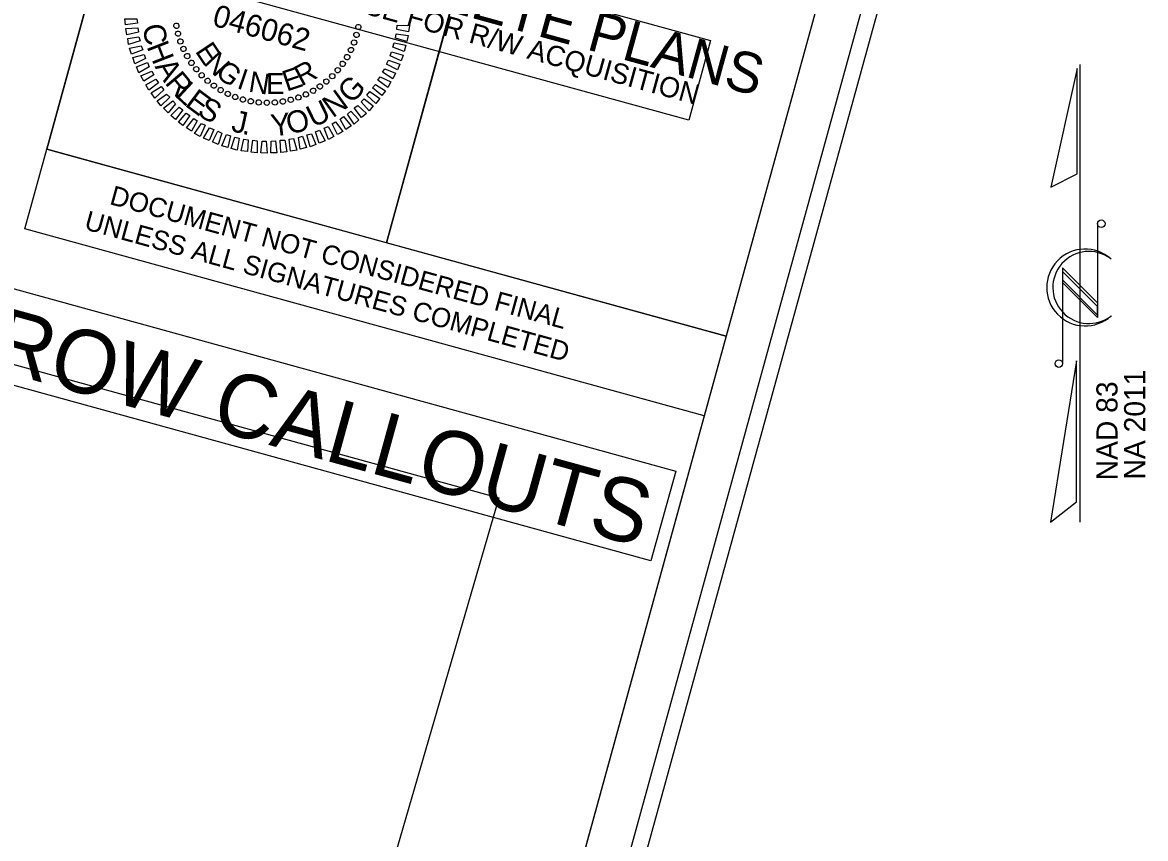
# Model space of a CAD drawing. Extents: x 1641192 to 2864602, y 841295 to 973236.
# Drawn here: x 1642843.9 to 1643162.7, y 842046.5 to 842278.3 of the extents above; entities that cross this region are included whole.
import ezdxf

# ---------------------------------------------------------------- set-up
doc = ezdxf.new("R2010")
doc.units = 0
for name, color, linetype in [('Default', 7, 'Continuous'), ('Old_Level_2', 7, 'Continuous'), ('Prop DSN White Annotation Label', 7, 'Continuous'), ('Sheet Clip Boundary CELL', 7, 'Continuous'), ('Sheet North Arrow CELL', 7, 'Continuous'), ('Sheet Plan CELL', 7, 'Continuous'), ('Sheet Plot Border Inside CELL', 7, 'Continuous'), ('Sheet Plot Border Outside CELL', 7, 'Continuous'), ('Sheet Sticker Exception Certification CELL', 7, 'Continuous'), ('Sheet Sticker Incomplete CELL', 7, 'Continuous')]:
    doc.layers.add(name, color=color, linetype=linetype)

msp = doc.modelspace()

# ---------------------------------------------------------------- linework, layer by layer
at = {"layer": 'Old_Level_2'}
for p, q in [((1642887.5, 842277.32), (1642887.5, 842277.32)), ((1642939.23, 842276.95), (1642939.23, 842276.95)), ((1642888.01, 842275.08), (1642888.01, 842275.08)), ((1642888.68, 842272.86), (1642888.68, 842272.86)), ((1642937.99, 842272.52), (1642937.99, 842272.52)), ((1642938.71, 842274.71), (1642938.71, 842274.71)), ((1642889.49, 842270.76), (1642889.49, 842270.76)), ((1642937.07, 842270.43), (1642937.07, 842270.43)), ((1642890.58, 842268.7), (1642890.58, 842268.7)), ((1642891.76, 842266.78), (1642891.76, 842266.78)), ((1642934.82, 842266.48), (1642934.82, 842266.48)), ((1642936.07, 842268.42), (1642936.07, 842268.42)), ((1642893.19, 842264.95), (1642893.19, 842264.95)), ((1642894.68, 842263.22), (1642894.68, 842263.22)), ((1642931.87, 842262.97), (1642931.87, 842262.97)), ((1642933.39, 842264.68), (1642933.39, 842264.68)), ((1642896.4, 842261.7), (1642896.4, 842261.7)), ((1642898.19, 842260.27), (1642898.19, 842260.27)), ((1642928.31, 842260.05), (1642928.31, 842260.05)), ((1642930.13, 842261.47), (1642930.13, 842261.47)), ((1642900.14, 842259.01), (1642900.14, 842259.01)), ((1642902.15, 842258.01), (1642902.15, 842258.01)), ((1642904.23, 842257.1), (1642904.23, 842257.1)), ((1642906.42, 842256.38), (1642906.42, 842256.38)), ((1642922.23, 842256.96), (1642922.23, 842256.96)), ((1642924.33, 842257.78), (1642924.33, 842257.78)), ((1642926.39, 842258.87), (1642926.39, 842258.87)), ((1642908.66, 842255.86), (1642908.66, 842255.86)), ((1642910.92, 842255.6), (1642910.92, 842255.6)), ((1642913.25, 842255.43), (1642913.25, 842255.43)), ((1642915.54, 842255.5), (1642915.54, 842255.5)), ((1642917.77, 842255.79), (1642917.77, 842255.79)), ((1642920.01, 842256.29), (1642920.01, 842256.29))]:
    msp.add_line(p, q, dxfattribs=at)
for points in [[(1642876.53, 842278.08), (1642873.1, 842277.56), (1642872.94, 842279.27), (1642876.29, 842279.27)], [(1642876.83, 842275.47), (1642873.45, 842274.71), (1642873.21, 842276.5), (1642876.61, 842276.71)], [(1642950.28, 842277.52), (1642953.75, 842277.38), (1642953.46, 842275.62), (1642950.17, 842276.25)], [(1642877.28, 842273.03), (1642873.99, 842271.98), (1642873.73, 842273.72), (1642876.92, 842274.15)], [(1642949.36, 842272.46), (1642952.69, 842271.77), (1642952.25, 842270.05), (1642949.05, 842271.25)], [(1642949.96, 842275.01), (1642953.36, 842274.57), (1642953.02, 842272.82), (1642949.75, 842273.77)], [(1642878.03, 842270.46), (1642874.85, 842269.23), (1642874.28, 842270.99), (1642877.58, 842271.66)], [(1642878.81, 842268.05), (1642875.78, 842266.56), (1642875.2, 842268.27), (1642878.45, 842269.17)], [(1642948.66, 842269.94), (1642951.93, 842269), (1642951.4, 842267.35), (1642948.25, 842268.75)], [(1642879.82, 842265.68), (1642876.91, 842264), (1642876.2, 842265.64), (1642879.37, 842266.88)], [(1642947.78, 842267.58), (1642950.95, 842266.44), (1642950.3, 842264.77), (1642947.22, 842266.43)], [(1642881.13, 842263.4), (1642878.34, 842261.58), (1642877.44, 842263.11), (1642880.58, 842264.41)], [(1642945.43, 842262.83), (1642948.41, 842261.37), (1642947.62, 842259.79), (1642944.76, 842261.87)], [(1642946.72, 842265.1), (1642949.75, 842263.89), (1642948.96, 842262.25), (1642946.04, 842264.14)], [(1642882.5, 842261.16), (1642879.74, 842259.06), (1642878.84, 842260.59), (1642881.73, 842262.17)], [(1642884.02, 842259.1), (1642881.43, 842256.8), (1642880.4, 842258.25), (1642883.24, 842260.06)], [(1642944.05, 842260.6), (1642946.96, 842258.88), (1642945.9, 842257.48), (1642943.22, 842259.68)], [(1642885.71, 842257.05), (1642883.18, 842254.57), (1642882.13, 842255.97), (1642884.75, 842257.94)], [(1642940.86, 842256.56), (1642943.42, 842254.55), (1642942.26, 842253.18), (1642940, 842255.75)], [(1642942.47, 842258.63), (1642945.31, 842256.66), (1642944.15, 842255.28), (1642941.67, 842257.64)], [(1642887.33, 842255.17), (1642885.22, 842252.64), (1642883.92, 842253.89), (1642886.52, 842256.03)], [(1642889.36, 842253.41), (1642887.33, 842250.75), (1642885.94, 842251.86), (1642888.39, 842254.25)], [(1642939.08, 842254.69), (1642941.53, 842252.45), (1642940.15, 842251.29), (1642938.04, 842253.99)], [(1642891.39, 842251.86), (1642889.41, 842248.97), (1642888.15, 842249.94), (1642890.32, 842252.52)], [(1642893.44, 842250.37), (1642891.87, 842247.42), (1642890.43, 842248.33), (1642892.47, 842251)], [(1642932.76, 842250.05), (1642934.81, 842247.31), (1642933.25, 842246.47), (1642931.75, 842249.45)], [(1642935.03, 842251.52), (1642937.16, 842248.87), (1642935.7, 842247.84), (1642934.09, 842250.79)], [(1642937.04, 842253.06), (1642939.34, 842250.63), (1642938, 842249.41), (1642936.14, 842252.26)], [(1642895.7, 842249.09), (1642894.35, 842245.92), (1642892.73, 842246.77), (1642894.7, 842249.61)], [(1642898.14, 842247.87), (1642896.85, 842244.74), (1642895.25, 842245.42), (1642896.96, 842248.33)], [(1642900.47, 842246.84), (1642899.42, 842243.6), (1642897.83, 842244.33), (1642899.3, 842247.35)], [(1642928.21, 842247.66), (1642929.76, 842244.67), (1642928.12, 842243.96), (1642927.08, 842247.25)], [(1642930.64, 842248.71), (1642932.29, 842245.91), (1642930.77, 842245), (1642929.49, 842248.25)], [(1642902.96, 842246.04), (1642902.12, 842242.74), (1642900.46, 842243.22), (1642901.76, 842246.4)], [(1642905.38, 842245.36), (1642904.79, 842242.01), (1642903.13, 842242.48), (1642904.18, 842245.72)], [(1642907.98, 842244.97), (1642907.7, 842241.58), (1642905.93, 842241.82), (1642906.72, 842245.13)], [(1642910.49, 842244.65), (1642910.46, 842241.2), (1642908.75, 842241.47), (1642909.23, 842244.81)], [(1642913.06, 842244.58), (1642913.31, 842241.12), (1642911.49, 842241.2), (1642911.93, 842244.6)], [(1642915.66, 842244.61), (1642916.05, 842241.28), (1642914.36, 842241.22), (1642914.51, 842244.53)], [(1642918.35, 842244.79), (1642918.91, 842241.51), (1642917.24, 842241.3), (1642917.01, 842244.81)], [(1642920.85, 842245.28), (1642921.74, 842242.03), (1642919.99, 842241.72), (1642919.62, 842245.11)], [(1642923.34, 842245.94), (1642924.51, 842242.72), (1642922.74, 842242.31), (1642922.22, 842245.58)], [(1642925.89, 842246.63), (1642927.11, 842243.57), (1642925.54, 842242.94), (1642924.62, 842246.31)]]:
    msp.add_lwpolyline(points, close=True, dxfattribs=at)
for centre, major_axis in [((1642887.54, 842277.31), (-0.742, -0.126)), ((1642888.02, 842275.07), (-0.729, -0.19)), ((1642938.69, 842274.73), (0.726, -0.2)), ((1642939.2, 842276.96), (0.741, -0.136)), ((1642888.69, 842272.88), (-0.709, -0.253)), ((1642937.99, 842272.55), (0.706, -0.262)), ((1642889.56, 842270.76), (-0.685, -0.314)), ((1642890.6, 842268.72), (-0.655, -0.372)), ((1642936.03, 842268.42), (0.65, -0.381)), ((1642937.1, 842270.44), (0.68, -0.323)), ((1642891.82, 842266.79), (-0.62, -0.428)), ((1642934.78, 842266.5), (0.614, -0.436)), ((1642893.2, 842264.96), (-0.58, -0.48)), ((1642894.73, 842263.26), (-0.536, -0.529)), ((1642931.82, 842263.01), (0.529, -0.536)), ((1642933.38, 842264.69), (0.574, -0.488)), ((1642896.41, 842261.71), (-0.488, -0.574)), ((1642898.21, 842260.3), (-0.436, -0.614)), ((1642900.13, 842259.06), (-0.381, -0.65)), ((1642926.36, 842258.88), (0.372, -0.655)), ((1642928.3, 842260.1), (0.428, -0.62)), ((1642930.12, 842261.48), (0.48, -0.58)), ((1642902.16, 842257.99), (-0.323, -0.68)), ((1642904.26, 842257.1), (-0.262, -0.706)), ((1642906.44, 842256.4), (-0.2, -0.726)), ((1642908.67, 842255.89), (-0.136, -0.741)), ((1642910.94, 842255.57), (-0.071, -0.75)), ((1642917.78, 842255.83), (0.126, -0.742)), ((1642920.02, 842256.31), (0.19, -0.729)), ((1642922.2, 842256.98), (0.253, -0.709)), ((1642924.32, 842257.84), (0.314, -0.685)), ((1642913.22, 842255.46), (-0.005, -0.753)), ((1642915.51, 842255.54), (0.061, -0.751))]:
    msp.add_ellipse(centre, major_axis=major_axis, ratio=0.999708, dxfattribs=at)
at = {"layer": 'Prop DSN White Annotation Label'}
msp.add_lwpolyline([(1642839.77, 842203.05), (1643029.31, 842150.89), (1643022.29, 842125.36), (1642832.75, 842177.53)], close=True, dxfattribs=at)
at = {"layer": 'Sheet Clip Boundary CELL'}
msp.add_lwpolyline([(1642834.84, 842332.26), (1642796.64, 842193.46), (1642979.12, 842143.25), (1642931.91, 841980.78), (1642684.68, 842016.94), (1642616.55, 841780.17), (1642867.94, 841712.2), (1642769.91, 841383), (1642620.74, 841424.05), (1642612.78, 841395.12), (1641412.11, 841725.54), (1641476.31, 841958.82), (1641627.07, 841958.82), (1641755.49, 842119.21), (1641752.38, 842181.83), (1641796.56, 842667.29)], dxfattribs=at)
at = {"layer": 'Sheet North Arrow CELL'}
for p, q in [((1643144.19, 842136.37), (1643144.19, 842266.37)), ((1643149.09, 842221.13), (1643149.09, 842194.45)), ((1643149.09, 842198.61), (1643139.15, 842208.55)), ((1643139.15, 842208.55), (1643139.15, 842181.43)), ((1643152.77, 842211.19), (1643152.91, 842211.09)), ((1643149.09, 842197.63), (1643139.15, 842207.57)), ((1643139.15, 842207.57), (1643139.15, 842205.13)), ((1643149.09, 842195.19), (1643139.15, 842205.13)), ((1643139.15, 842205.13), (1643149.09, 842195.19)), ((1643149.09, 842194.45), (1643139.15, 842204.39)), ((1643149.09, 842195.19), (1643149.09, 842197.63))]:
    msp.add_line(p, q, dxfattribs=at)
for points in [[(1643143.29, 842265.23), (1643135.87, 842231.47), (1643143.29, 842235.23)], [(1643143.13, 842182.17), (1643135.77, 842136.37), (1643143.13, 842142.17)]]:
    msp.add_lwpolyline(points, close=True, dxfattribs=at)
for centre in [(1643150.15, 842221.11), (1643138.09, 842181.39)]:
    msp.add_circle(centre, 1.06, dxfattribs=at)
for centre, radius, start, end in [((1643145.57, 842203), 10.92, 47.84, 312.3941), ((1643146.63, 842203), 10.24, 53.095, 308.6287)]:
    msp.add_arc(centre, radius, start, end, dxfattribs=at)
at = {"layer": 'Sheet Plan CELL'}
msp.add_line((1642977.06, 842324.21), (1642947.23, 842215.77), dxfattribs=at)
for points in [[(1643083.47, 842333.88), (1641637.2, 842731.89), (1641358.6, 841719.52), (1642804.85, 841321.52)], [(1641358.6, 841719.52), (1641637.16, 842731.87), (1642890.57, 842386.98), (1642850.76, 842242.29), (1643043.63, 842189.2), (1642804.85, 841321.52)], [(1642880.6, 842350.75), (1642977.06, 842324.21), (1642947.21, 842215.73), (1642850.76, 842242.29)], [(1642977.06, 842324.21), (1643073.47, 842297.69), (1643043.63, 842189.2), (1642947.21, 842215.73)]]:
    msp.add_lwpolyline(points, close=True, dxfattribs=at)
at = {"layer": 'Sheet Plot Border Inside CELL'}
msp.add_lwpolyline([(1641209.95, 841757.82), (1642816.23, 841315.8), (1643096.16, 842332.97), (1641489.87, 842775.01)], close=True, dxfattribs=at)
at = {"layer": 'Sheet Plot Border Outside CELL'}
msp.add_lwpolyline([(1641192.11, 841741.99), (1642815.27, 841295.31), (1643105.8, 842351.06), (1641482.64, 842797.74)], close=True, dxfattribs=at)
msp.add_lwpolyline([(1641192.11, 841741.99), (1642815.27, 841295.31), (1643105.8, 842351.06), (1641482.64, 842797.74)], close=True, dxfattribs=at)
at = {"layer": 'Sheet Sticker Exception Certification CELL'}
for p, q in [((1642844.53, 842219.63), (1642850.76, 842242.29)), ((1642844.53, 842219.63), (1642850.76, 842242.29)), ((1642850.76, 842242.29), (1643043.63, 842189.22)), ((1642850.76, 842242.29), (1643043.63, 842189.22)), ((1643037.4, 842166.56), (1642844.53, 842219.63)), ((1643037.4, 842166.56), (1642844.53, 842219.63)), ((1643043.63, 842189.2), (1643037.39, 842166.55)), ((1643043.63, 842189.2), (1643037.39, 842166.55))]:
    msp.add_line(p, q, dxfattribs=at)
at = {"layer": 'Sheet Sticker Incomplete CELL'}
msp.add_lwpolyline([(1642891.27, 842289.47), (1642897.51, 842312.13), (1643039.24, 842273.13), (1643033, 842250.47)], close=True, dxfattribs=at)

# ---------------------------------------------------------------- texts
at = {"layer": 'Default'}
for s, rotation, p in [('C', 281.8134, (1642877.83, 842277.23)), ('H', 291.2571, (1642879.04, 842271.46)), ('A', 301.0969, (1642881.29, 842265.73)), ('R', 309.8096, (1642884.07, 842261.05)), ('G', 46.4133, (1642937.26, 842254.9)), ('L', 317.1818, (1642886.96, 842257.46)), ('E', 323.366, (1642889.72, 842254.75)), ('S', 330.3726, (1642893.18, 842252.06)), ('N', 35.8424, (1642931.94, 842250.98)), ('O', 14.6548, (1642919.6, 842246.35)), ('U', 26.0482, (1642926.45, 842248.27)), ('J', 347.6456, (1642902.88, 842247.39)), ('Y', 6.8561, (1642914.75, 842245.84)), ('.', 352.8275, (1642906.02, 842246.58))]:
    msp.add_text(s, height=6.27, rotation=rotation, dxfattribs=at).set_placement(p)
at = {"layer": 'Old_Level_2'}
for s, height, rotation, p in [('046062', 6.275, 344.6135, (1642897.46, 842277.44)), ('E', 5.9, 303.8904, (1642892.72, 842270.09)), ('N', 5.9, 313.2475, (1642895.06, 842266.58)), ('G', 5.9, 322.6037, (1642898.32, 842263.31)), ('R', 5.9, 28.0949, (1642923.07, 842260.04)), ('I', 5.9, 341.3147, (1642904.47, 842259.69)), ('N', 5.9, 350.6699, (1642907.82, 842258.66)), ('E', 5.9, 0.0253, (1642912.99, 842257.99)), ('E', 5.9, 18.7376, (1642918.87, 842258.58))]:
    msp.add_text(s, height=height, rotation=rotation, dxfattribs=at).set_placement(p)
at = {"layer": 'Prop DSN White Annotation Label'}
msp.add_text('ROW CALLOUTS', height=18, rotation=344.6132, dxfattribs=at).set_placement((1642833.65, 842180.34))
at = {"layer": 'Sheet North Arrow CELL'}
for s, p in [('NA 2011', (1643162.63, 842148.48)), ('NAD 83', (1643154.76, 842148.24))]:
    msp.add_text(s, height=6, rotation=90, dxfattribs=at).set_placement(p)
at = {"layer": 'Sheet Sticker Exception Certification CELL'}
for s, p in [('DOCUMENT NOT CONSIDERED FINAL', (1642868.33, 842226.73)), ('DOCUMENT NOT CONSIDERED FINAL', (1642868.33, 842226.73)), ('UNLESS ALL SIGNATURES COMPLETED', (1642861.11, 842219.59)), ('UNLESS ALL SIGNATURES COMPLETED', (1642861.11, 842219.59))]:
    msp.add_text(s, height=5.5, rotation=344.6135, dxfattribs=at).set_placement(p)
at = {"layer": 'Sheet Sticker Incomplete CELL'}
for s, height, p in [('INCOMPLETE PLANS', 11.52, (1642903.01, 842298.38)), ('DO NOT USE FOR R/W ACQUISITION', 5.76, (1642904.29, 842290.82))]:
    msp.add_text(s, height=height, rotation=344.6135, dxfattribs=at).set_placement(p)

doc.saveas('drawing.dxf')
